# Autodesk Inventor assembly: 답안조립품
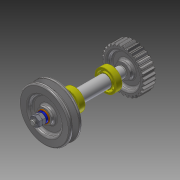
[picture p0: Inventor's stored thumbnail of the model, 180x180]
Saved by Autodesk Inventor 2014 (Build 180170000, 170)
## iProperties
Created: 2016-07
Part Number: 답안조립품
Document SubType Name: Assembly
Designer: Administrator
Author: Administrator
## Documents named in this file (13)
- C:\Users\Administrator\Desktop\460707V1003\답안조립품.iam
- C:\Users\Administrator\Desktop\460707V1003\본체.ipt
- C:\Users\Administrator\Desktop\460707V1003\커버.ipt
- C:\Users\Administrator\Desktop\460707V1003\볼트 M4 x 12.ipt
- C:\Users\Administrator\Desktop\460707V1003\오일 실 15 25 7.ipt
- C:\Users\Administrator\Desktop\460707V1003\베어링 15 x 32 x 9.ipt
- C:\Users\Administrator\Desktop\460707V1003\축.ipt
- C:\Users\Administrator\Desktop\460707V1003\키 3 x 3 x 12.ipt
- C:\Users\Administrator\Desktop\460707V1003\V벨트풀리.ipt
- C:\Users\Administrator\Desktop\460707V1003\와셔 8x17.ipt
- C:\Users\Administrator\Desktop\460707V1003\스프링와셔 8.ipt
- C:\Users\Administrator\Desktop\460707V1003\너트 M 8.ipt
- C:\Users\Administrator\Desktop\460707V1003\스퍼기어.ipt
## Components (11 placed, 3 different names)
1. KS B 2023 6002 - 15 x 32 x 9:1
2. KS B 2023 6002 - 15 x 32 x 9:2
3. V벨트풀리:1
4. ISO 4762 M4 x 12:1
5. ISO 4762 M4 x 12:2
6. ISO 4762 M4 x 12:3
7. ISO 4762 M4 x 12:4
8. ISO 4762 M4 x 12:5
9. ISO 4762 M4 x 12:6
10. ISO 4762 M4 x 12:7
11. ISO 4762 M4 x 12:8
